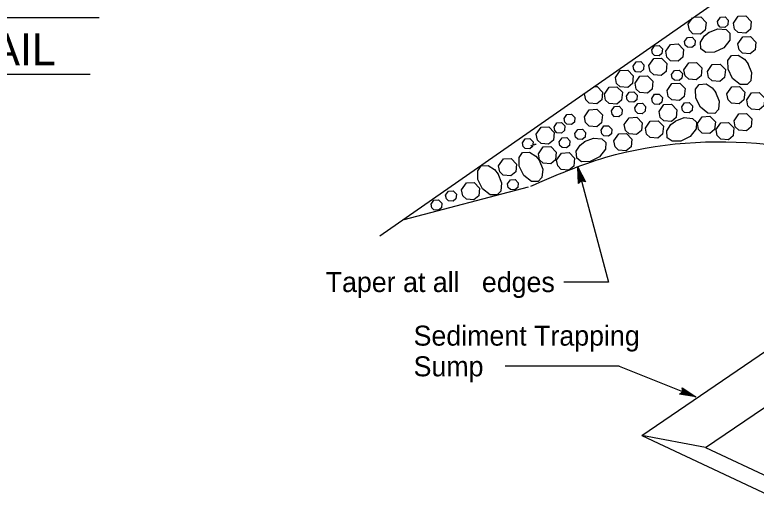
# Model space of a CAD drawing. Extents: x 6707406 to 6714471, y 1868570 to 1872341.
# Drawn here: x 6710320.4 to 6710587.1, y 1870221.6 to 1870399.1 of the extents above; entities that cross this region are included whole.
import ezdxf

# ---------------------------------------------------------------- set-up
doc = ezdxf.new("R2010")
doc.units = 0
for name, color, linetype in [('56 Stg 3 Anno', 7, 'Continuous'), ('57 Undefined', 7, 'Continuous'), ('60 Nongeo Data', 7, 'Continuous')]:
    doc.layers.add(name, color=color, linetype=linetype)

msp = doc.modelspace()

# ---------------------------------------------------------------- linework, layer by layer
at = {"layer": '56 Stg 3 Anno'}
for p, q in [((6710522.92, 1870344.3), (6710533.94, 1870302.96)), ((6710523.16, 1870338.4), (6710522.92, 1870344.3)), ((6710522.92, 1870344.3), (6710522.92, 1870344.3)), ((6710522.92, 1870344.3), (6710525.64, 1870339.06)), ((6710523.44, 1870338.69), (6710523.26, 1870343.02)), ((6710523.27, 1870343.01), (6710525.25, 1870339.19)), ((6710523.72, 1870339), (6710523.6, 1870341.74)), ((6710523.6, 1870341.74), (6710524.88, 1870339.27)), ((6710523.99, 1870339.25), (6710523.94, 1870340.46)), ((6710523.94, 1870340.46), (6710524.49, 1870339.4)), ((6710524.21, 1870339.48), (6710523.16, 1870338.4)), ((6710523.16, 1870338.4), (6710523.16, 1870338.4)), ((6710525.64, 1870339.06), (6710524.21, 1870339.48)), ((6710525.64, 1870339.06), (6710525.64, 1870339.06)), ((6710533.94, 1870302.96), (6710517.96, 1870302.96)), ((6710537.79, 1870272.64), (6710496.85, 1870272.64)), ((6710537.79, 1870272.64), (6710565.34, 1870261.62)), ((6710560.7, 1870263.47), (6710560.47, 1870264.95)), ((6710560.47, 1870264.95), (6710560.47, 1870264.95)), ((6710560.47, 1870264.95), (6710565.34, 1870261.62)), ((6710559.51, 1870262.57), (6710560.7, 1870263.47)), ((6710565.34, 1870261.62), (6710559.51, 1870262.57)), ((6710559.51, 1870262.57), (6710559.51, 1870262.57)), ((6710564.09, 1870262.11), (6710559.85, 1870262.81)), ((6710562.87, 1870262.6), (6710560.13, 1870263.05)), ((6710561.64, 1870263.1), (6710560.47, 1870263.29)), ((6710560.53, 1870264.56), (6710564.11, 1870262.11)), ((6710560.61, 1870264.15), (6710562.87, 1870262.6)), ((6710560.65, 1870263.78), (6710561.64, 1870263.1)), ((6710565.34, 1870261.62), (6710565.34, 1870261.62))]:
    msp.add_line(p, q, dxfattribs=at)
at = {"layer": '57 Undefined'}
for p, q in [((6710161.92, 1870398.18), (6710350.68, 1870398.18)), ((6710163.84, 1870377.76), (6710347.49, 1870377.76))]:
    msp.add_line(p, q, dxfattribs=at)
at = {"layer": '60 Nongeo Data'}
for p, q in [((6710451.72, 1870319.56), (6710722.11, 1870508.07)), ((6710460.47, 1870325.47), (6710505.18, 1870337.2)), ((6710545.91, 1870247.74), (6710596.21, 1870282.03)), ((6710568.89, 1870243.43), (6710600.37, 1870264.89)), ((6710545.91, 1870247.74), (6710601.56, 1870221.61)), ((6710568.89, 1870243.43), (6710545.91, 1870247.74)), ((6710568.89, 1870243.43), (6710600.34, 1870228.66))]:
    msp.add_line(p, q, dxfattribs=at)
for points in [[(6710564.53, 1870398.21), (6710567.14, 1870398.36), (6710569.07, 1870396.35), (6710568.79, 1870393.55), (6710567.08, 1870392.12), (6710564.34, 1870392.32), (6710563.05, 1870393.57), (6710562.63, 1870395.72)], [(6710573.18, 1870396.74), (6710574.22, 1870398.22), (6710575.89, 1870398.32), (6710577.05, 1870397.12), (6710576.88, 1870395.44), (6710575.85, 1870394.58), (6710574.2, 1870394.7), (6710573.43, 1870395.45), (6710573.18, 1870396.74)], [(6710578.88, 1870396.1), (6710580.62, 1870398.57), (6710583.4, 1870398.73), (6710585.33, 1870396.73), (6710585.05, 1870393.93), (6710583.33, 1870392.5), (6710580.59, 1870392.7), (6710579.3, 1870393.95), (6710578.88, 1870396.1)], [(6710562.63, 1870395.72), (6710564.22, 1870397.99)], [(6710564.22, 1870397.99), (6710564.22, 1870397.99)], [(6710570, 1870392.78), (6710573.25, 1870394.07), (6710576.24, 1870393.81), (6710577.66, 1870392.46), (6710577.62, 1870390.03), (6710575.46, 1870387.28), (6710572.13, 1870385.61), (6710568.99, 1870385.55), (6710567.22, 1870386.81), (6710567.05, 1870389.31), (6710568.49, 1870391.55), (6710570.13, 1870392.86)], [(6710561.3, 1870389.46), (6710562.34, 1870390.94), (6710564.01, 1870391.04), (6710565.17, 1870389.84), (6710565, 1870388.15), (6710563.97, 1870387.3), (6710562.33, 1870387.42), (6710561.55, 1870388.17), (6710561.3, 1870389.46)], [(6710580.52, 1870388.69), (6710582.25, 1870391.17), (6710585.03, 1870391.32), (6710586.96, 1870389.32), (6710586.68, 1870386.52), (6710584.97, 1870385.09), (6710582.23, 1870385.29), (6710580.94, 1870386.54), (6710580.52, 1870388.69)], [(6710549.5, 1870386.51), (6710550.54, 1870388), (6710552.21, 1870388.09), (6710553.36, 1870386.89), (6710553.2, 1870385.21), (6710552.17, 1870384.35), (6710550.52, 1870384.47), (6710549.75, 1870385.22), (6710549.5, 1870386.51)], [(6710554.55, 1870386), (6710556.29, 1870388.48), (6710559.07, 1870388.64), (6710561, 1870386.64), (6710560.72, 1870383.83), (6710559, 1870382.4), (6710556.26, 1870382.6), (6710554.97, 1870383.85), (6710554.55, 1870386)], [(6710542.84, 1870380.68), (6710543.88, 1870382.17), (6710545.55, 1870382.26), (6710546.7, 1870381.06), (6710546.54, 1870379.38), (6710545.51, 1870378.52), (6710543.86, 1870378.64), (6710543.09, 1870379.39), (6710542.84, 1870380.68)], [(6710548.52, 1870380.9), (6710550.26, 1870383.38), (6710553.03, 1870383.54), (6710554.96, 1870381.53), (6710554.68, 1870378.73), (6710552.97, 1870377.3), (6710550.23, 1870377.5), (6710548.94, 1870378.75), (6710548.52, 1870380.9)], [(6710584.14, 1870381.64), (6710585.43, 1870378.39), (6710585.17, 1870375.4), (6710583.82, 1870373.98), (6710581.39, 1870374.02), (6710578.63, 1870376.18), (6710576.97, 1870379.51), (6710576.91, 1870382.65), (6710578.17, 1870384.42), (6710580.67, 1870384.59), (6710582.91, 1870383.15), (6710584.22, 1870381.51)], [(6710561.11, 1870379.34), (6710562.85, 1870381.81), (6710565.63, 1870381.97), (6710567.56, 1870379.97), (6710567.28, 1870377.17), (6710565.56, 1870375.74), (6710562.82, 1870375.94), (6710561.53, 1870377.19), (6710561.11, 1870379.34)], [(6710569.58, 1870378.76), (6710571.32, 1870381.24), (6710574.1, 1870381.39), (6710576.03, 1870379.39), (6710575.75, 1870376.59), (6710574.04, 1870375.16), (6710571.29, 1870375.36), (6710570, 1870376.61), (6710569.58, 1870378.76)], [(6710536.45, 1870376.56), (6710538.19, 1870379.04), (6710540.96, 1870379.19), (6710542.89, 1870377.19), (6710542.61, 1870374.39), (6710540.9, 1870372.96), (6710538.16, 1870373.16), (6710536.87, 1870374.41), (6710536.45, 1870376.56)], [(6710543.52, 1870374.55), (6710545.26, 1870377.03), (6710548.04, 1870377.19), (6710549.97, 1870375.18), (6710549.69, 1870372.38), (6710547.98, 1870370.95), (6710545.23, 1870371.15), (6710543.94, 1870372.4), (6710543.52, 1870374.55)], [(6710556.68, 1870377.61), (6710557.73, 1870379.1), (6710559.39, 1870379.19), (6710560.55, 1870377.99), (6710560.38, 1870376.31), (6710559.36, 1870375.45), (6710557.71, 1870375.57), (6710556.93, 1870376.32), (6710556.68, 1870377.61)], [(6710555.06, 1870371.92), (6710556.8, 1870374.39), (6710559.58, 1870374.55), (6710561.51, 1870372.55), (6710561.23, 1870369.75), (6710559.51, 1870368.32), (6710556.77, 1870368.52), (6710555.48, 1870369.77), (6710555.06, 1870371.92)], [(6710572.51, 1870371.3), (6710573.8, 1870368.04), (6710573.54, 1870365.05), (6710572.19, 1870363.63), (6710569.76, 1870363.68), (6710567.01, 1870365.83), (6710565.34, 1870369.17), (6710565.29, 1870372.31), (6710566.54, 1870374.07), (6710569.05, 1870374.24), (6710571.28, 1870372.81), (6710572.59, 1870371.16)], [(6710528.75, 1870373.26), (6710529.87, 1870373.33), (6710531.8, 1870371.33), (6710531.52, 1870368.52), (6710529.8, 1870367.09), (6710527.06, 1870367.29), (6710525.77, 1870368.54), (6710525.35, 1870370.69)], [(6710532.5, 1870370.59), (6710534.24, 1870373.06), (6710537.02, 1870373.22), (6710538.95, 1870371.22), (6710538.67, 1870368.42), (6710536.96, 1870366.99), (6710534.21, 1870367.19), (6710532.93, 1870368.44), (6710532.51, 1870370.59)], [(6710576.54, 1870370.7), (6710578.28, 1870373.17), (6710581.06, 1870373.33), (6710582.99, 1870371.33), (6710582.71, 1870368.52), (6710580.99, 1870367.09), (6710578.25, 1870367.29), (6710576.96, 1870368.54), (6710576.54, 1870370.69)], [(6710540.42, 1870369.83), (6710541.46, 1870371.31), (6710543.13, 1870371.4), (6710544.29, 1870370.2), (6710544.12, 1870368.52), (6710543.09, 1870367.67), (6710541.45, 1870367.78), (6710540.67, 1870368.53), (6710540.42, 1870369.82)], [(6710549.5, 1870369.03), (6710550.54, 1870370.51), (6710552.21, 1870370.6), (6710553.36, 1870369.4), (6710553.2, 1870367.72), (6710552.17, 1870366.86), (6710550.52, 1870366.98), (6710549.75, 1870367.73), (6710549.5, 1870369.02)], [(6710583.7, 1870368.5), (6710585.44, 1870370.98), (6710588.21, 1870371.14), (6710590.15, 1870369.14), (6710589.87, 1870366.33), (6710588.15, 1870364.9), (6710585.41, 1870365.1), (6710584.12, 1870366.35), (6710583.7, 1870368.5)], [(6710535.04, 1870364.6), (6710536.08, 1870366.09), (6710537.75, 1870366.19), (6710538.9, 1870364.98), (6710538.74, 1870363.3), (6710537.71, 1870362.44), (6710536.06, 1870362.56), (6710535.29, 1870363.31), (6710535.04, 1870364.6)], [(6710543.46, 1870365.68), (6710544.51, 1870367.17), (6710546.17, 1870367.26), (6710547.33, 1870366.06), (6710547.16, 1870364.38), (6710546.13, 1870363.52), (6710544.49, 1870363.64), (6710543.72, 1870364.39), (6710543.46, 1870365.68)], [(6710552.15, 1870364.34), (6710553.88, 1870366.82), (6710556.66, 1870366.97), (6710558.59, 1870364.97), (6710558.31, 1870362.17), (6710556.6, 1870360.74), (6710553.86, 1870360.94), (6710552.57, 1870362.19), (6710552.15, 1870364.34)], [(6710560.31, 1870365.99), (6710561.35, 1870367.47), (6710563.02, 1870367.57), (6710564.18, 1870366.36), (6710564.01, 1870364.68), (6710562.98, 1870363.83), (6710561.34, 1870363.95), (6710560.56, 1870364.7), (6710560.31, 1870365.99)], [(6710525.31, 1870362.46), (6710527.05, 1870364.94), (6710529.83, 1870365.1), (6710531.76, 1870363.09), (6710531.48, 1870360.29), (6710529.77, 1870358.86), (6710527.02, 1870359.06), (6710525.73, 1870360.31), (6710525.31, 1870362.46)], [(6710579.15, 1870361.01), (6710580.89, 1870363.48), (6710583.66, 1870363.64), (6710585.59, 1870361.64), (6710585.32, 1870358.83), (6710583.6, 1870357.41), (6710580.86, 1870357.6), (6710579.57, 1870358.86), (6710579.15, 1870361.01)], [(6710517.99, 1870361.75), (6710519.03, 1870363.24), (6710520.7, 1870363.33), (6710521.86, 1870362.13), (6710521.69, 1870360.45), (6710520.66, 1870359.59), (6710519.01, 1870359.71), (6710518.24, 1870360.46), (6710517.99, 1870361.75)], [(6710536, 1870362.26), (6710535.94, 1870362.53)], [(6710537.77, 1870362.76), (6710537.91, 1870362.87)], [(6710539.64, 1870359.63), (6710541.38, 1870362.1), (6710544.15, 1870362.26), (6710546.09, 1870360.26), (6710545.81, 1870357.45), (6710544.09, 1870356.03), (6710541.35, 1870356.23), (6710540.06, 1870357.48), (6710539.64, 1870359.63)], [(6710547.26, 1870358.36), (6710549, 1870360.84), (6710551.78, 1870361), (6710553.7, 1870359), (6710553.43, 1870356.19), (6710551.71, 1870354.76), (6710548.97, 1870354.96), (6710547.68, 1870356.21), (6710547.26, 1870358.36)], [(6710557.9, 1870360.82), (6710561.16, 1870362.11), (6710564.14, 1870361.85), (6710565.57, 1870360.5), (6710565.52, 1870358.08), (6710563.36, 1870355.32), (6710560.03, 1870353.65), (6710556.89, 1870353.6), (6710555.12, 1870354.86), (6710554.96, 1870357.36), (6710556.39, 1870359.59), (6710558.03, 1870360.9)], [(6710565.96, 1870359.97), (6710567.7, 1870362.45), (6710570.48, 1870362.61), (6710572.41, 1870360.61), (6710572.13, 1870357.8), (6710570.41, 1870356.37), (6710567.67, 1870356.57), (6710566.38, 1870357.82), (6710565.96, 1870359.97)], [(6710507.98, 1870356.16), (6710509.72, 1870358.64), (6710512.5, 1870358.8), (6710514.43, 1870356.8), (6710514.15, 1870353.99), (6710512.43, 1870352.56), (6710509.69, 1870352.76), (6710508.4, 1870354.01), (6710507.98, 1870356.16)], [(6710514.4, 1870358.73), (6710515.44, 1870360.22), (6710517.11, 1870360.31), (6710518.27, 1870359.11), (6710518.1, 1870357.43), (6710517.07, 1870356.57), (6710515.43, 1870356.69), (6710514.65, 1870357.44), (6710514.4, 1870358.73)], [(6710531.31, 1870357.63), (6710532.35, 1870359.12), (6710534.02, 1870359.21), (6710535.18, 1870358.01), (6710535.01, 1870356.33), (6710533.98, 1870355.47), (6710532.33, 1870355.59), (6710531.56, 1870356.34), (6710531.31, 1870357.63)], [(6710572.64, 1870357.78), (6710574.38, 1870360.26), (6710577.16, 1870360.41), (6710579.09, 1870358.41), (6710578.81, 1870355.61), (6710577.1, 1870354.18), (6710574.35, 1870354.38), (6710573.06, 1870355.63), (6710572.65, 1870357.78)], [(6710521.85, 1870356.4), (6710522.9, 1870357.89), (6710524.56, 1870357.99), (6710525.72, 1870356.78), (6710525.55, 1870355.1), (6710524.52, 1870354.24), (6710522.88, 1870354.36), (6710522.11, 1870355.11), (6710521.85, 1870356.4)], [(6710535.9, 1870353.77), (6710537.64, 1870356.25), (6710540.42, 1870356.41), (6710542.35, 1870354.4), (6710542.07, 1870351.6), (6710540.35, 1870350.17), (6710537.61, 1870350.37), (6710536.32, 1870351.62), (6710535.9, 1870353.77)], [(6710502.98, 1870352.99), (6710504.02, 1870354.47), (6710505.69, 1870354.57), (6710506.85, 1870353.37), (6710506.68, 1870351.68), (6710505.65, 1870350.83), (6710504.01, 1870350.95), (6710503.23, 1870351.7), (6710502.98, 1870352.99)], [(6710516.23, 1870353.38), (6710517.28, 1870354.87), (6710518.94, 1870354.96), (6710520.1, 1870353.76), (6710519.94, 1870352.08), (6710518.91, 1870351.22), (6710517.26, 1870351.34), (6710516.49, 1870352.09), (6710516.24, 1870353.38)], [(6710525.3, 1870353.48), (6710528.55, 1870354.77), (6710531.54, 1870354.51), (6710532.96, 1870353.16), (6710532.92, 1870350.73), (6710530.76, 1870347.97), (6710527.43, 1870346.31), (6710524.29, 1870346.25), (6710522.52, 1870347.51), (6710522.36, 1870350.01), (6710523.79, 1870352.25), (6710525.43, 1870353.56)], [(6710506.31, 1870351.88), (6710506.21, 1870351.99), (6710506.16, 1870352.2)], [(6710507.19, 1870352.2), (6710507.4, 1870352.51), (6710507.87, 1870352.53), (6710507.93, 1870352.47)], [(6710508.75, 1870349.09), (6710510.49, 1870351.56), (6710513.27, 1870351.72), (6710515.2, 1870349.72), (6710514.92, 1870346.91), (6710513.2, 1870345.49), (6710510.46, 1870345.69), (6710509.17, 1870346.94), (6710508.75, 1870349.09)], [(6710509, 1870346.77), (6710510.3, 1870343.52), (6710510.04, 1870340.53), (6710508.69, 1870339.11), (6710506.26, 1870339.16), (6710503.51, 1870341.31), (6710501.84, 1870344.64), (6710501.78, 1870347.78), (6710503.04, 1870349.55), (6710505.54, 1870349.72), (6710507.78, 1870348.28), (6710509.09, 1870346.64)], [(6710515.27, 1870346.87), (6710517.01, 1870349.35), (6710519.79, 1870349.51), (6710521.72, 1870347.5), (6710521.44, 1870344.7), (6710519.73, 1870343.27), (6710516.98, 1870343.47), (6710515.69, 1870344.72), (6710515.28, 1870346.87)], [(6710494.18, 1870341.96), (6710495.47, 1870338.7), (6710495.22, 1870335.71), (6710493.87, 1870334.29), (6710491.44, 1870334.34), (6710488.68, 1870336.49), (6710487.02, 1870339.83), (6710486.96, 1870342.97), (6710488.22, 1870344.74), (6710490.72, 1870344.9), (6710492.96, 1870343.47), (6710494.27, 1870341.83)], [(6710494.41, 1870344.77), (6710496.15, 1870347.24), (6710498.93, 1870347.4), (6710500.86, 1870345.4), (6710500.58, 1870342.59), (6710498.86, 1870341.17), (6710496.12, 1870341.37), (6710494.83, 1870342.62), (6710494.41, 1870344.77)], [(6710497.65, 1870338.28), (6710498.69, 1870339.76), (6710500.36, 1870339.86), (6710501.52, 1870338.66), (6710501.35, 1870336.97), (6710500.32, 1870336.12), (6710498.68, 1870336.24), (6710497.9, 1870336.99), (6710497.65, 1870338.28)], [(6710481.12, 1870336.13), (6710482.85, 1870338.61), (6710485.63, 1870338.76), (6710487.56, 1870336.76), (6710487.28, 1870333.96), (6710485.57, 1870332.53), (6710482.83, 1870332.73), (6710481.53, 1870333.98), (6710481.12, 1870336.13)], [(6710475.38, 1870334.21), (6710476.42, 1870335.7), (6710478.09, 1870335.79), (6710479.25, 1870334.59), (6710479.08, 1870332.91), (6710478.05, 1870332.05), (6710476.41, 1870332.17), (6710475.63, 1870332.92), (6710475.38, 1870334.21)], [(6710470.14, 1870330.95), (6710471.19, 1870332.44), (6710472.85, 1870332.53), (6710474.01, 1870331.33), (6710473.84, 1870329.65), (6710472.81, 1870328.79), (6710471.17, 1870328.91), (6710470.39, 1870329.66), (6710470.14, 1870330.95)]]:
    msp.add_lwpolyline(points, dxfattribs=at)
msp.add_spline([(6710505.99, 1870337.51), (6710532.99, 1870347.83), (6710590.83, 1870352.57), (6710625.79, 1870346.13), (6710776.97, 1870278.77)], degree=3, dxfattribs=at)

# ---------------------------------------------------------------- texts
at = {"layer": '57 Undefined'}
for s, height, p in [('STEEL PANEL DETAIL', 11.5203, (6710173.28, 1870380.98)), ('Taper at all   edges', 7.2002, (6710432.23, 1870299.36)), ('Sediment Trapping', 7.2002, (6710463.85, 1870280.08)), ('Sump', 7.2, (6710463.85, 1870269.04))]:
    msp.add_text(s, height=height, dxfattribs=at).set_placement(p)

doc.saveas('drawing.dxf')
